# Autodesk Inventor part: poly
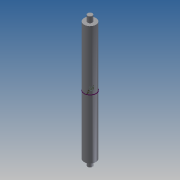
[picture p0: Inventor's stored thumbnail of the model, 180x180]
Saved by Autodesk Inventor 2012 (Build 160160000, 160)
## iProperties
Created: 2012-04
Part Number: poly
Material: Default
Document SubType Name: Modeling
Designer: win32
Mass: 997.456 g
Surface Area: 856.084 cm^2
Volume: 997.456 cm^3
Density: 1 g/cm^3
Author: win32
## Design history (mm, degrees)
sketch "Sketch1"
  geometry: C1 r 25 at (0, 0); C2 r 10 at (0, 0); 1 further point
  constraints: 2 centre point, 2 coincident
  dimensions: "d0" = 50 diameter of C1; "d1" = 20 diameter of C2
extrude "Extrusion1" new body sketch "Sketch1" stored distance "d2" = 500; taper "d3" = 0 deg
extrude "Extrusion2" join sketch "Sketch1" stored distance "d4" = 550; taper "d5" = 0 deg
body "Solid1"
